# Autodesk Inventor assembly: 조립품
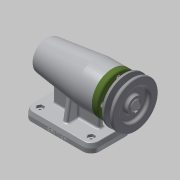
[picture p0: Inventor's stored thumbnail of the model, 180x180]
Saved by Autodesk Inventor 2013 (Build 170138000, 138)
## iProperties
Created: 2017-01
Part Number: 조립품
Document SubType Name: Assembly
Designer: Administrator
Author: Administrator
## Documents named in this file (12)
- C:\Users\Administrator\Desktop\470107V1017\조립품.iam
- C:\Users\Administrator\Desktop\470107V1017\V벨트풀리.ipt
- C:\Users\Administrator\Desktop\470107V1017\멈춤나사 M3x8.ipt
- C:\Users\Administrator\Desktop\470107V1017\베어링 6004.ipt
- C:\Users\Administrator\Desktop\470107V1017\베어링 51202.ipt
- C:\Users\Administrator\Desktop\470107V1017\본체.ipt
- C:\Users\Administrator\Desktop\470107V1017\볼트 M4 x 12.ipt
- C:\Users\Administrator\Desktop\470107V1017\어댑터슬리브.ipt
- C:\Users\Administrator\Desktop\470107V1017\오일 실.ipt
- C:\Users\Administrator\Desktop\470107V1017\축.ipt
- C:\Users\Administrator\Desktop\470107V1017\커버.ipt
- C:\Users\Administrator\Desktop\470107V1017\키 5 x 5 x 16.ipt
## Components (6 placed, 2 different names)
1. V벨트풀리:1
2. ISO 4762 M4 x 12:1
3. ISO 4762 M4 x 12:2
4. ISO 4762 M4 x 12:3
5. ISO 4762 M4 x 12:4
6. ISO 4762 M4 x 12:5
